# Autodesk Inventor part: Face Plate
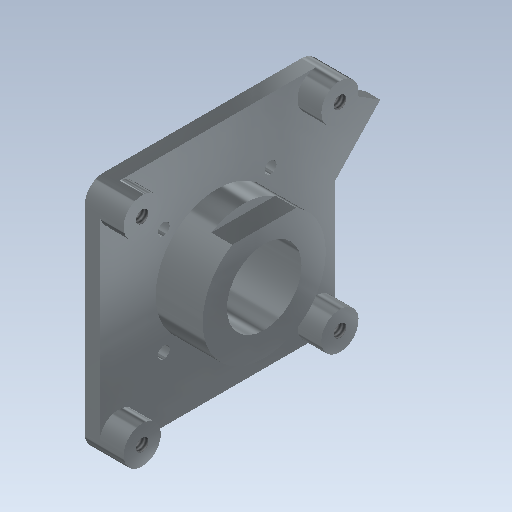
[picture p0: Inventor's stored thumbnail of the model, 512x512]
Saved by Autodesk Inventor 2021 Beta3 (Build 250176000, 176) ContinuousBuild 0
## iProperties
Created: 2012-08
Part Number: Face Plate
Material: PC/ABS Plastic
Document SubType Name: Modeling
Designer: John
Density: 1.493 g/cm^3
Mass: 11.4166 g
Surface Area: 57.4511 cm^2
Volume: 7.64678 cm^3
Appearance: Zinc
Author: John
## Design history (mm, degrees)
sketch "Sketch1"
  geometry: L1 (0, 0)-(40.005, 0); L2 (40.005, 0)-(40.005, 40.005); L3 (40.005, 40.005)-(0, 40.005); L4 (0, 40.005)-(0, 0)
  constraints: 8 end point, 2 parallel, 1 horizontal, 1 perpendicular
  dimensions: "d0" = 40.005 distance of L3.end L2.end; "d1" = 40.005 distance of L1.end L2.end (= d0)
extrude "Extrusion1" new body sketch "Sketch1" distance "d2" = 2.54; taper "d3" = 0 deg
fillet "Fillet1" dims "d4" = 3.175
sketch "Sketch2"
  geometry: C1 r 3.175 at (-3.175, 3.175); A1 r 3.175 centre (-3.175, 36.83) between (0, 36.83) and (-3.175, 40.005) reference; A2 r 3.175 centre (-36.83, 36.83) between (-36.83, 40.005) and (-40.005, 36.83) reference; A3 r 3.175 centre (-36.83, 3.175) between (-40.005, 3.175) and (-36.83, 0) reference; A4 r 3.175 centre (-3.175, 3.175) between (-3.175, 0) and (0, 3.175) reference; 4 further points
  constraints: 4 coincident, 3 horizontal alignment, 1 centre point, 1 concentric, 6 other
extrude "Extrusion2" join sketch "Sketch2" distance "d5" = 4.064; taper "d6" = 0 deg
sketch "Sketch3"
  geometry: C1 r 3.175 at (0, 0) reference; C2 r 3.175 at (0, 33.655) reference; C3 r 3.175 at (33.655, 33.655) reference; C4 r 3.175 at (33.655, 0) reference; 1 further point
hole "Hole1" sketch "Sketch3" at (0, 33.655), (33.655, 33.655), (33.655, 0), (0, 0) diameter "d7" = 2.159; stored, may be unused: countersink angle "d11" = 82 deg, drill point angle "d13" = 118 deg; dims "d8" = 19.05, "d9" = 9.525, "d10" = 6.35, "d12" = 25.4
sketch "Sketch4"
  geometry: L1 (-10.909, 10.909)-(-29.096, 10.909); L2 (-29.096, 10.909)-(-29.096, 29.096); L3 (-29.096, 29.096)-(-10.909, 29.096); L4 (-10.909, 29.096)-(-10.909, 10.909); L5 (-36.83, 3.175)-(-3.175, 36.83); L6 (-10.909, 10.909)-(-29.096, 29.096); A1 r 3.175 centre (-3.175, 36.83) between (-3.175, 40.005) and (0, 36.83) reference; A2 r 3.175 centre (-36.83, 3.175) between (-36.83, 0) and (-40.005, 3.175) reference; 2 further points
  constraints: 12 end point, 2 midpoint, 2 parallel, 2 perpendicular, 1 horizontal
  dimensions: "d14" = 18.1864 distance of L2.end L3.end
hole "Hole2" sketch "Sketch4" at (-29.096, 10.909), (-29.096, 29.096), (-10.909, 10.909), (-10.909, 29.096) diameter "d16" = 2.032; stored, may be unused: countersink angle "d20" = 82 deg, drill point angle "d22" = 118 deg; dims "d17" = 19.05, "d18" = 9.525, "d19" = 6.35, "d21" = 25.4
sketch "Sketch5"
  geometry: L1 (-29.096, 29.096)-(-10.909, 10.909); C1 r 1.016 at (-10.909, 10.909) reference; C2 r 1.016 at (-29.096, 29.096) reference; C3 r 10.477 at (-20.002, 20.002); 1 further point
  constraints: 2 end point, 1 centre point, 1 midpoint
  dimensions: "d23" = 20.955 diameter of C3
extrude "Extrusion3" join sketch "Sketch5" distance "d25" = 8.001; taper "d26" = 0 deg
sketch "Sketch6"
  geometry: C1 r 10.477 at (0, 0) reference; C2 r 6.35 at (0, 0); 1 further point
  constraints: 1 centre point, 1 coincident
  dimensions: "d27" = 6.35 radius of C2
extrude "Extrusion4" cut sketch "Sketch6" extent not by distance; stored distance "d28" = 8.001; taper "d29" = 0 deg
sketch "Sketch7"
  geometry: L1 (-10.477, -5.442)-(-8.954, -5.442); L2 (-8.954, -5.442)-(-8.954, 5.442); L3 (-8.954, 5.442)-(-10.477, 5.442); L4 (-10.477, 5.442)-(-10.477, -5.442); A1 r 10.477 centre (0, 0) between (-8.954, 5.442) and (-8.954, -5.442) reference; 1 further point
  constraints: 8 end point, 2 parallel, 2 point on circle, 1 horizontal, 1 perpendicular, 1 tangent
  dimensions: "d30" = 19.431 dimension on A1 L2
extrude "Extrusion5" cut sketch "Sketch7" distance "d31" = 3.556; taper "d32" = 0 deg
sketch "Sketch10"
  geometry: L1 (3.175, 40.005)-(36.83, 40.005) reference; L2 (21.539, 40.005)-(29.743, 47.752); L3 (29.743, 47.752)-(34.62, 40.005); L4 (36.83, 0)-(3.175, 0) reference; L5 (40.005, 36.83)-(40.005, 3.175) reference; 1 further point
  constraints: 4 end point, 2 point on line
  dimensions: "d43" = 5.3848 distance from line of L3.end L5; "d44" = 10.2616 distance from line of L5 L2.end; "d45" = 18.4658 distance from line of L2.start L5; "d46" = 47.752 distance from line of L4 L2.end
extrude "Extrusion8" join sketch "Sketch10" stored distance "d41" = 3.556; taper "d42" = 0 deg
body "Solid1"
node "Projected Loop1"
node "Projected Loop2"
node "Projected Loop3"
